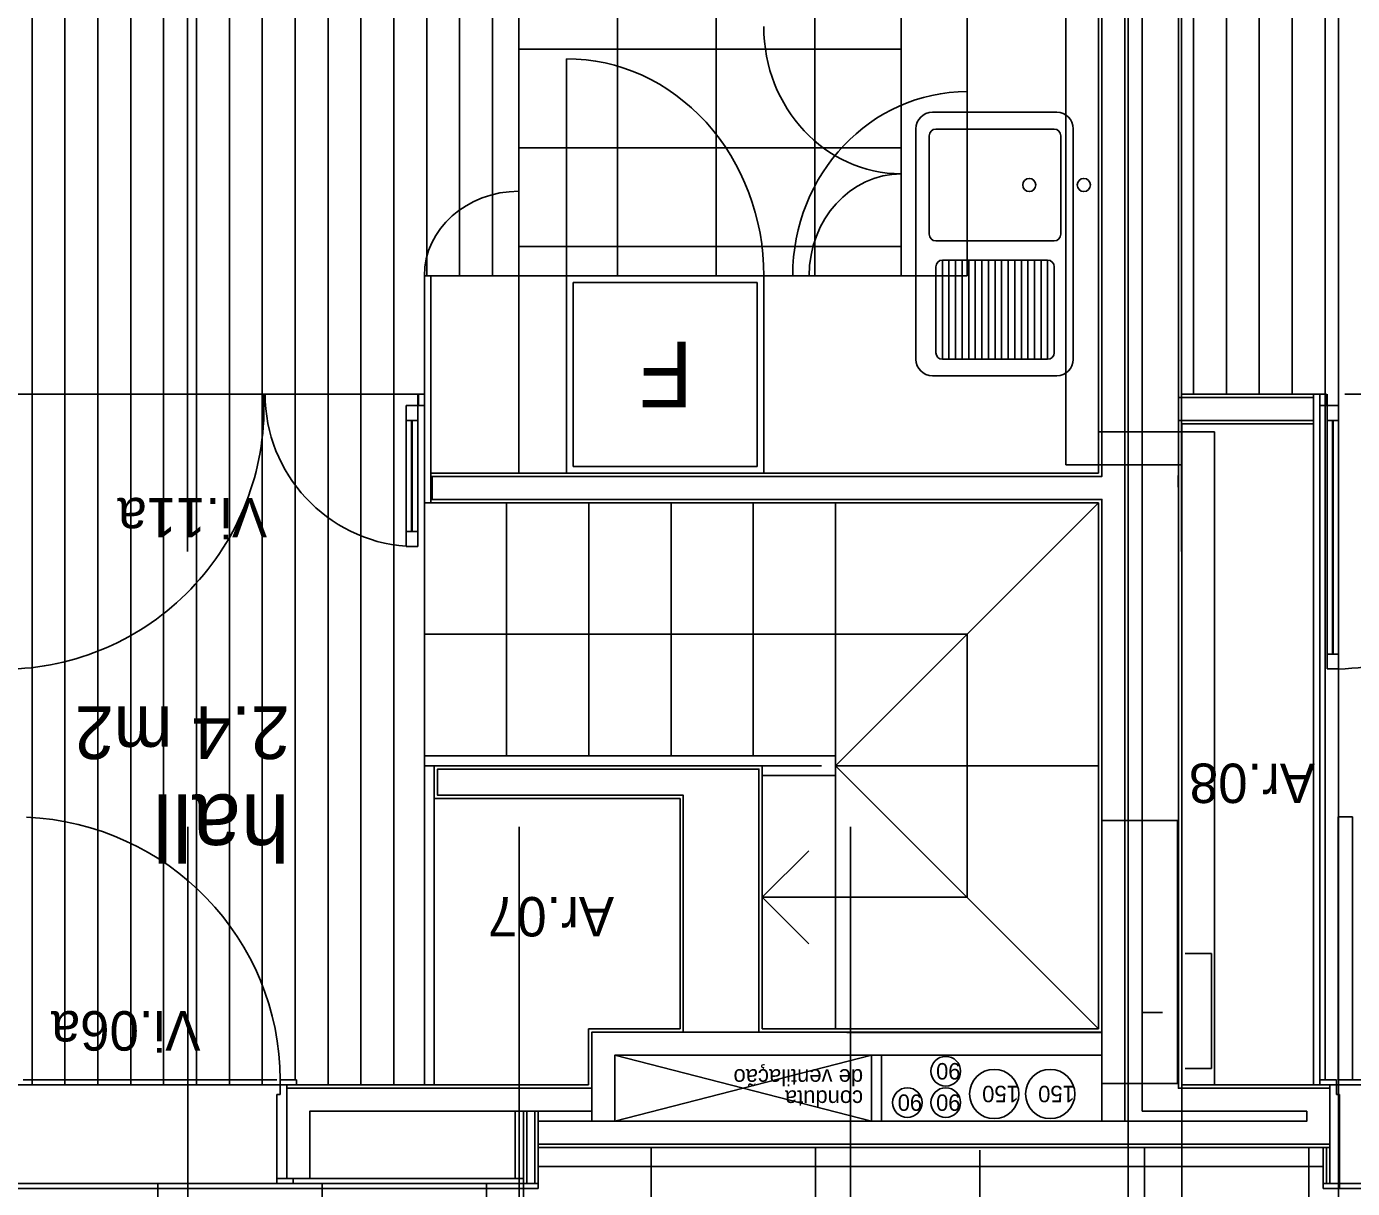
# Model space of a CAD drawing. Extents: x 1248 to 1356, y -443 to -224.
# Drawn here: x 1308.119 to 1312.151, y -237.241 to -233.707 of the extents above; entities that cross this region are included whole.
import ezdxf

# ---------------------------------------------------------------- set-up
doc = ezdxf.new("R2010")
doc.units = 0
for name, color, linetype in [('corte', 7, 'Continuous'), ('estereoctomias', 7, 'Continuous'), ('Level 1', 7, 'Continuous'), ('Level 10', 7, 'Continuous'), ('Level 11', 7, 'Continuous'), ('Level 13', 7, 'Continuous'), ('Level 2', 7, 'Continuous'), ('Level 21', 7, 'Continuous'), ('Level 3', 7, 'Continuous'), ('Level 36', 7, 'Continuous'), ('Level 4', 7, 'Continuous'), ('Level 40', 7, 'Continuous'), ('Level 41', 7, 'Continuous'), ('Level 59', 7, 'Continuous'), ('Level 60', 7, 'Continuous'), ('mob-fixo', 7, 'Continuous'), ('projeccao', 7, 'Continuous'), ('revestimentos', 7, 'Continuous'), ('vermelhos-cont', 7, 'Continuous'), ('vermelhos-tracej', 7, 'Continuous')]:
    doc.layers.add(name, color=color, linetype=linetype)

msp = doc.modelspace()

# ---------------------------------------------------------------- linework, layer by layer
at = {"layer": 'corte'}
for p, q in [((1311.6219, -235.1452), (1311.6219, -231.934)), ((1311.6219, -234.8352), (1311.6219, -231.934)), ((1311.389, -232.2659), (1311.389, -235.0752)), ((1311.459, -232.7639), (1311.459, -236.1213)), ((1311.5119, -236.1213), (1311.5119, -232.7639)), ((1311.6219, -236.9359), (1311.6219, -234.9052)), ((1311.389, -235.1452), (1311.389, -237.0363)), ((1311.6219, -236.9359), (1311.6219, -235.1452)), ((1311.459, -236.1213), (1311.459, -237.0363)), ((1311.5119, -236.1213), (1311.5119, -237.0059)), ((1309.8383, -236.9359), (1309.8383, -236.7652)), ((1309.9083, -237.0363), (1309.9083, -236.8352)), ((1309.9083, -236.8352), (1311.389, -236.8352)), ((1310.689, -236.8352), (1310.689, -237.0363)), ((1310.719, -236.8352), (1310.719, -237.0363)), ((1312.0819, -237.1063), (1312.0819, -236.9259)), ((1308.9104, -237.2109), (1308.9104, -236.9359)), ((1308.9804, -237.2109), (1308.9804, -237.0059)), ((1309.8383, -237.0363), (1309.8383, -237.0059)), ((1312.0119, -237.0363), (1312.0119, -237.0059)), ((1309.6754, -237.1063), (1309.6754, -237.0363)), ((1311.459, -237.0363), (1312.0119, -237.0363)), ((1311.4019, -237.1063), (1309.6754, -237.1063)), ((1308.9804, -237.2109), (1308.9104, -237.2109))]:
    msp.add_line(p, q, dxfattribs=at)
msp.add_lwpolyline([(1311.389, -236.9213), (1311.619, -236.9213), (1311.619, -236.1213), (1311.389, -236.1213)], close=True, dxfattribs=at)
at = {"layer": 'estereoctomias'}
for p, q in [((1308.8804, -237.2259), (1308.0804, -237.2259)), ((1312.9119, -237.2259), (1312.1119, -237.2259))]:
    msp.add_line(p, q, dxfattribs=at)
for points in [[(1311.459, -232.7639), (1311.459, -236.1213), (1311.389, -236.1213), (1311.389, -235.1452), (1309.3528, -235.1452), (1309.3528, -235.0752), (1311.389, -235.0752), (1311.389, -232.7639)], [(1311.5119, -232.7639), (1311.6219, -232.7639), (1311.6219, -235.0752), (1311.6214, -235.073), (1311.6219, -235.1452), (1311.6219, -235.1452), (1311.6219, -236.1213), (1311.5119, -236.1213)], [(1311.5119, -232.7639), (1311.6219, -232.7639), (1311.6219, -234.8352), (1312.0319, -234.8352), (1312.0319, -234.9052), (1311.6219, -234.9052), (1311.6219, -236.1213), (1311.5119, -236.1213)], [(1310.3464, -236.7652), (1310.3464, -235.9652), (1309.369, -235.9652), (1309.369, -236.0452), (1310.1164, -236.0452), (1310.1164, -236.7652)], [(1311.389, -236.7652), (1311.389, -236.8352), (1309.9083, -236.8352), (1309.9083, -237.0363), (1309.8383, -237.0363), (1309.8383, -236.7652)], [(1310.719, -236.8352), (1310.719, -237.0363), (1310.689, -237.0363), (1310.689, -236.8352)], [(1311.5119, -237.0059), (1311.5119, -236.9213), (1311.6219, -236.9213), (1311.6219, -236.9359), (1312.0819, -236.9359), (1312.0819, -237.1063), (1309.6754, -237.1063), (1309.6754, -237.0363), (1312.0119, -237.0363), (1312.0119, -237.0059)], [(1311.459, -237.0363), (1311.459, -236.9213), (1311.389, -236.9213), (1311.389, -237.0363)], [(1309.8383, -236.9359), (1309.8383, -237.0059), (1308.9804, -237.0059), (1308.9804, -237.2109), (1308.9104, -237.2109), (1308.9104, -236.9359)]]:
    msp.add_lwpolyline(points, close=True, dxfattribs=at)
at = {"layer": 'Level 1'}
for p, q in [((1312.0319, -234.9152), (1312.0319, -234.8252)), ((1311.6219, -234.8352), (1312.0319, -234.8352)), ((1312.0319, -234.9052), (1311.6219, -234.9052)), ((1309.349, -235.0652), (1309.349, -235.1552)), ((1311.389, -235.0752), (1309.349, -235.0752)), ((1311.389, -235.1452), (1309.349, -235.1452)), ((1310.3464, -235.9652), (1309.369, -235.9652)), ((1309.369, -235.9652), (1309.369, -236.0452)), ((1310.3464, -236.7652), (1310.3464, -235.9652)), ((1309.369, -236.0452), (1310.1164, -236.0452)), ((1310.1164, -236.7652), (1310.1164, -236.0452)), ((1311.51, -236.7052), (1311.57, -236.7052)), ((1311.5129, -236.7052), (1311.5729, -236.7052)), ((1309.8383, -236.7652), (1311.389, -236.7672)), ((1309.8383, -236.9359), (1308.9104, -236.9359)), ((1311.6219, -236.9359), (1312.0819, -236.9359)), ((1309.8383, -237.0059), (1308.9804, -237.0059)), ((1311.5119, -237.0059), (1312.0119, -237.0059)), ((1309.8383, -237.0363), (1309.6754, -237.0363)), ((1311.389, -237.0363), (1309.9083, -237.0363)), ((1312.0819, -237.1063), (1309.8512, -237.1063))]:
    msp.add_line(p, q, dxfattribs=at)
at = {"layer": 'Level 10'}
for p, q in [((1308.1362, -232.2759), (1308.1362, -236.9259)), ((1308.2362, -232.2759), (1308.2362, -236.9259)), ((1308.3362, -232.2759), (1308.3362, -236.9259)), ((1308.4362, -232.2759), (1308.4362, -236.9259)), ((1308.5362, -232.2759), (1308.5362, -236.9259)), ((1308.6362, -232.2759), (1308.6362, -236.9259)), ((1308.7362, -232.2759), (1308.7362, -236.9259)), ((1308.8362, -232.2759), (1308.8362, -236.9259)), ((1308.9362, -232.2759), (1308.9362, -236.9109)), ((1309.0362, -232.2759), (1309.0362, -236.9259)), ((1309.1362, -232.2759), (1309.1362, -236.9259)), ((1309.2362, -232.2759), (1309.2362, -236.9259)), ((1309.3362, -232.2759), (1309.3362, -234.4652)), ((1309.4362, -232.2759), (1309.4362, -234.4652)), ((1309.5362, -232.2759), (1309.5362, -234.4652)), ((1309.6162, -232.2759), (1309.6162, -234.4652)), ((1309.9162, -232.2759), (1309.9162, -234.4652)), ((1310.2162, -232.2759), (1310.2162, -234.4652)), ((1310.5162, -232.2759), (1310.5162, -234.4652)), ((1311.6677, -232.2759), (1311.6677, -234.8252)), ((1311.7677, -232.2759), (1311.7677, -234.8252)), ((1311.8677, -232.2759), (1311.8677, -234.8252)), ((1311.9677, -232.2759), (1311.9677, -234.8252)), ((1312.0677, -232.2759), (1312.0677, -236.9109)), ((1308.8904, -236.9259), (1308.0704, -236.9259)), ((1312.9219, -236.9259), (1312.1019, -236.9259)), ((1310.0183, -237.1163), (1310.0183, -238.724)), ((1310.5183, -237.1163), (1310.5183, -238.724)), ((1311.0183, -237.124), (1311.0183, -238.724)), ((1311.5183, -237.1163), (1311.5183, -238.724)), ((1312.0183, -237.1163), (1312.0183, -238.724)), ((1309.6754, -237.174), (1312.0619, -237.174)), ((1308.5183, -237.2259), (1308.5183, -238.624)), ((1309.0183, -237.2259), (1309.0183, -238.624)), ((1309.5183, -237.2259), (1309.5183, -238.624))]:
    msp.add_line(p, q, dxfattribs=at)
at = {"layer": 'Level 11'}
for p, q in [((1310.3412, -234.4852), (1309.7812, -234.4852)), ((1309.7812, -234.4852), (1309.7812, -235.0452)), ((1310.3412, -234.4852), (1310.3412, -235.0452)), ((1309.7812, -235.0452), (1310.3412, -235.0452))]:
    msp.add_line(p, q, dxfattribs=at)
at = {"layer": 'Level 13'}
for p, q in [((1309.349, -234.4652), (1309.329, -234.4652)), ((1309.329, -234.4652), (1309.329, -235.1552)), ((1309.349, -234.4652), (1309.349, -235.0652)), ((1309.3109, -234.8602), (1309.3109, -234.8252)), ((1309.3109, -234.8252), (1309.3309, -234.8252)), ((1312.0519, -234.8252), (1312.0319, -234.8252)), ((1312.0719, -234.8252), (1312.0519, -234.8252)), ((1312.0519, -234.8252), (1312.0519, -236.9259)), ((1312.0719, -234.8252), (1312.0719, -234.8602)), ((1309.2739, -234.8602), (1309.3089, -234.8602)), ((1309.2739, -234.8602), (1309.2739, -235.288)), ((1309.3089, -234.8602), (1309.3089, -235.288)), ((1309.3109, -234.8602), (1309.3309, -234.8602)), ((1312.0719, -234.8602), (1312.0519, -234.8602)), ((1312.0739, -234.8602), (1312.0739, -235.661)), ((1312.1089, -234.8602), (1312.0739, -234.8602)), ((1312.1089, -234.8602), (1312.1089, -235.661)), ((1309.2739, -234.9052), (1309.3089, -234.9052)), ((1312.0319, -234.9152), (1312.0319, -236.9259)), ((1312.1089, -234.9052), (1312.0739, -234.9052)), ((1312.0519, -235.0652), (1312.0519, -236.9259)), ((1309.349, -235.1552), (1309.329, -235.1552)), ((1309.3089, -235.243), (1309.2739, -235.243)), ((1309.3089, -235.288), (1309.2739, -235.288)), ((1312.1089, -235.616), (1312.0739, -235.616)), ((1312.1089, -235.661), (1312.0739, -235.661)), ((1309.329, -235.9552), (1309.329, -236.9259)), ((1309.359, -235.9552), (1309.329, -235.9552)), ((1309.359, -235.9552), (1309.359, -236.9259)), ((1312.1069, -236.1109), (1312.1069, -236.9109)), ((1312.1509, -236.1109), (1312.1069, -236.1109)), ((1312.1509, -236.9109), (1312.1509, -236.1109)), ((1308.8904, -236.9109), (1308.9404, -236.9109)), ((1308.8904, -236.9549), (1308.8904, -236.9259)), ((1308.9104, -236.9259), (1308.9104, -237.2109)), ((1312.0819, -236.9259), (1312.0819, -237.2259)), ((1312.1019, -236.9549), (1312.1019, -236.9259)), ((1312.1069, -236.9109), (1312.1509, -236.9109)), ((1308.8804, -237.2109), (1308.8804, -236.9549)), ((1308.8804, -236.9549), (1308.8904, -236.9549)), ((1312.1119, -236.9549), (1312.1019, -236.9549)), ((1312.1119, -236.9549), (1312.1119, -237.2259)), ((1309.6304, -237.0059), (1309.6304, -237.2259)), ((1309.6404, -237.2259), (1309.6404, -237.0059)), ((1309.6654, -237.2259), (1309.6654, -237.0059)), ((1309.6754, -237.2059), (1309.6754, -237.0059)), ((1312.0619, -237.2409), (1312.0619, -237.1163)), ((1312.0719, -237.1163), (1312.0719, -237.2259)), ((1309.6304, -237.2109), (1308.8804, -237.2109)), ((1308.8804, -237.2109), (1308.8804, -237.2259)), ((1308.9304, -237.2109), (1308.9304, -237.2259)), ((1309.6304, -237.2109), (1309.6304, -237.2259)), ((1309.6754, -237.2059), (1309.6754, -237.2259)), ((1308.9304, -237.2259), (1308.8804, -237.2259)), ((1309.6304, -237.2259), (1308.9204, -237.2259)), ((1309.6304, -237.2259), (1308.9204, -237.2259)), ((1309.6304, -237.2259), (1308.9304, -237.2259)), ((1309.6304, -237.2259), (1309.6304, -237.2409)), ((1309.6304, -237.2259), (1309.6754, -237.2259)), ((1309.6304, -237.2409), (1309.6754, -237.2409)), ((1309.6754, -237.2259), (1309.6754, -237.2409)), ((1312.0619, -237.2259), (1312.1119, -237.2259)), ((1312.1119, -237.2409), (1312.0619, -237.2409)), ((1312.1119, -237.2259), (1312.1119, -237.2409))]:
    msp.add_line(p, q, dxfattribs=at)
for points in [[(1308.9404, -236.9109), (1308.8904, -236.9109), (1308.8904, -236.9259), (1308.9404, -236.9259)], [(1312.1019, -236.9259), (1312.0519, -236.9259), (1312.0519, -236.9109), (1312.1019, -236.9109)]]:
    msp.add_lwpolyline(points, close=True, dxfattribs=at)
at = {"layer": 'Level 2'}
for p, q in [((1310.779, -232.2759), (1310.779, -234.4652)), ((1311.2441, -234.0191), (1310.8841, -234.0191)), ((1310.8641, -234.0391), (1310.8641, -234.3391)), ((1311.2641, -234.3391), (1311.2641, -234.0391)), ((1310.8841, -234.3591), (1311.2441, -234.3591)), ((1311.2241, -234.4175), (1310.9041, -234.4175)), ((1310.9041, -234.4175), (1310.9041, -234.7191)), ((1310.9241, -234.4175), (1310.9241, -234.7191)), ((1310.9441, -234.4175), (1310.9441, -234.7191)), ((1310.9641, -234.4175), (1310.9641, -234.7191)), ((1310.9841, -234.4175), (1310.9841, -234.7191)), ((1311.0041, -234.4175), (1311.0041, -234.7191)), ((1311.0241, -234.4175), (1311.0241, -234.7191)), ((1311.0441, -234.4175), (1311.0441, -234.7191)), ((1311.0641, -234.4175), (1311.0641, -234.7191)), ((1311.0841, -234.4175), (1311.0841, -234.7191)), ((1311.1041, -234.4175), (1311.1041, -234.7191)), ((1311.1241, -234.4175), (1311.1241, -234.7191)), ((1311.1441, -234.4175), (1311.1441, -234.7191)), ((1311.1641, -234.4175), (1311.1641, -234.7191)), ((1311.1841, -234.4175), (1311.1841, -234.7191)), ((1311.2041, -234.4175), (1311.2041, -234.7191)), ((1311.2241, -234.4175), (1311.2241, -234.7191)), ((1310.779, -234.4652), (1309.349, -234.4652)), ((1310.7662, -234.4652), (1309.4862, -234.4652)), ((1310.7662, -234.4652), (1309.4862, -234.4652)), ((1309.7612, -234.4652), (1309.7612, -235.0652)), ((1309.7612, -234.4652), (1309.7612, -235.0652)), ((1310.3612, -234.4652), (1310.3612, -235.0652)), ((1310.3612, -234.4652), (1310.3612, -235.0652)), ((1310.8841, -234.4375), (1310.8841, -234.6991)), ((1311.2441, -234.4375), (1311.2441, -234.6991)), ((1311.2241, -234.7191), (1310.9041, -234.7191)), ((1309.329, -235.9552), (1309.329, -235.1552)), ((1309.579, -235.9252), (1309.579, -235.1552)), ((1309.829, -235.9252), (1309.829, -235.1552)), ((1310.079, -235.9252), (1310.079, -235.1552)), ((1310.329, -235.9252), (1310.329, -235.1552)), ((1310.579, -235.9252), (1310.579, -235.1552)), ((1310.579, -235.9552), (1311.379, -235.1552)), ((1309.329, -235.5552), (1310.979, -235.5552)), ((1310.979, -236.3552), (1310.979, -235.5552)), ((1310.579, -235.9252), (1309.329, -235.9252)), ((1310.5364, -235.9552), (1309.329, -235.9552)), ((1310.5364, -235.9552), (1309.3317, -235.9552)), ((1310.579, -235.9252), (1310.579, -235.9852)), ((1311.379, -235.9552), (1310.579, -235.9552)), ((1310.579, -235.9552), (1311.379, -236.7552)), ((1310.579, -235.9852), (1310.3564, -235.9852)), ((1310.579, -236.7552), (1310.579, -235.9852)), ((1310.4978, -236.2137), (1310.3564, -236.3552)), ((1310.979, -236.3552), (1310.3564, -236.3552)), ((1310.4978, -236.4966), (1310.3564, -236.3552))]:
    msp.add_line(p, q, dxfattribs=at)
for points in [[(1310.8736, -233.9679), (1311.252, -233.9679)], [(1310.8236, -234.7193), (1310.8236, -234.0179)], [(1311.302, -234.0179), (1311.302, -234.7193)], [(1311.252, -234.7693), (1310.8736, -234.7693)]]:
    msp.add_lwpolyline(points, dxfattribs=at)
for centre in [(1311.1681, -234.1891), (1311.3341, -234.1891)]:
    msp.add_circle(centre, 0.0199, dxfattribs=at)
for centre, radius, start, end in [((1310.8736, -234.0179), 0.05, 90, 180), ((1311.252, -234.0179), 0.05, 360, 90), ((1310.8841, -234.0391), 0.02, 90, 180), ((1311.2441, -234.0391), 0.02, 360, 90), ((1310.8841, -234.3391), 0.02, 180, 270), ((1311.2441, -234.3391), 0.02, 270, 0), ((1310.9041, -234.4375), 0.02, 90, 180), ((1311.2241, -234.4375), 0.02, 0, 90), ((1310.9041, -234.6991), 0.02, 180, 270), ((1311.2241, -234.6991), 0.02, 270, 0), ((1310.8736, -234.7193), 0.05, 180, 270), ((1311.252, -234.7193), 0.05, 270, 360)]:
    msp.add_arc(centre, radius, start, end, dxfattribs=at)
at = {"layer": 'Level 21'}
for p, q in [((1309.6162, -233.7759), (1310.779, -233.7759)), ((1309.6162, -234.0759), (1310.779, -234.0759)), ((1309.6162, -234.3759), (1310.779, -234.3759))]:
    msp.add_line(p, q, dxfattribs=at)
at = {"layer": 'Level 3'}
for p in [(1310.979, -232.2759), (1310.779, -234.4652)]:
    msp.add_line(p, (1310.979, -234.4652), dxfattribs=at)
at = {"layer": 'Level 36'}
for p, q in [((1309.2904, -234.9052), (1309.2904, -235.243)), ((1309.2924, -234.9052), (1309.2924, -235.243)), ((1312.0904, -234.9052), (1312.0904, -235.616)), ((1312.0924, -234.9052), (1312.0924, -235.616))]:
    msp.add_line(p, q, dxfattribs=at)
at = {"layer": 'Level 4'}
for p, q in [((1309.7612, -233.8052), (1309.7612, -234.4652)), ((1309.6162, -234.4652), (1309.6162, -234.2052)), ((1309.6162, -234.4652), (1309.6162, -235.0652)), ((1308.0404, -234.8252), (1309.3294, -234.8252)), ((1309.3089, -234.8602), (1309.3089, -234.8252)), ((1312.0739, -234.8602), (1312.0739, -234.8252)), ((1312.1273, -234.8252), (1313.4163, -234.8252)), ((1311.6419, -236.5259), (1311.7219, -236.5259)), ((1311.7219, -236.5259), (1311.7219, -236.8759)), ((1311.6419, -236.8759), (1311.7219, -236.8759)), ((1308.8804, -236.9109), (1308.1094, -236.9109)), ((1312.9119, -236.9109), (1312.1409, -236.9109)), ((1309.6054, -237.0059), (1309.6054, -237.2109)), ((1308.0804, -237.2409), (1309.6304, -237.2409)), ((1309.6304, -237.2259), (1309.6304, -237.9259)), ((1312.1119, -237.2409), (1313.6619, -237.2409))]:
    msp.add_line(p, q, dxfattribs=at)
for centre, major_axis, ratio, start_param, end_param in [((1310.779, -233.7072), (0, -0.448), 0.933036, 4.712389, 6.283185), ((1309.7612, -234.4652), (0, -0.66), 0.909091, 1.570796, 3.141593), ((1310.979, -234.4652), (0, -0.56), 0.946429, 3.141593, 4.712389), ((1310.779, -234.4652), (0, -0.31), 0.903226, 3.141593, 4.712389), ((1308.0844, -236.9109), (-0.806, 0), 0.992512, 3.141593, 4.668897)]:
    msp.add_ellipse(centre, major_axis=major_axis, ratio=ratio, start_param=start_param, end_param=end_param, dxfattribs=at)
at = {"layer": 'Level 41'}
for p, q in [((1310.689, -237.0363), (1309.9083, -236.8352)), ((1309.9083, -237.0363), (1310.689, -236.8352))]:
    msp.add_line(p, q, dxfattribs=at)
for centre, radius in [((1310.9143, -236.8843), 0.045), ((1311.0616, -236.9535), 0.075), ((1311.2318, -236.9535), 0.075), ((1310.7975, -236.9797), 0.045), ((1310.9143, -236.9797), 0.045)]:
    msp.add_circle(centre, radius, dxfattribs=at)
at = {"layer": 'Level 59'}
msp.add_lwpolyline([(1312.108, -245.3846), (1306.9649, -245.3846), (1306.9649, -230.4331), (1312.108, -230.4331)], close=True, dxfattribs=at)
at = {"layer": 'mob-fixo'}
for p, q in [((1311.279, -232.609), (1311.279, -235.0402)), ((1311.379, -234.9402), (1311.7319, -234.9402)), ((1311.7319, -236.9259), (1311.7319, -234.9402)), ((1311.279, -235.0402), (1311.6319, -235.0402))]:
    msp.add_line(p, q, dxfattribs=at)
at = {"layer": 'projeccao'}
for centre, radius, start, end in [((1308.0452, -234.8658), 0.7962, 272.1092, 2.9297), ((1309.3089, -234.8252), 0.4641, 180, 265.6752), ((1312.0796, -234.8658), 0.7962, 272.1092, 2.9297)]:
    msp.add_arc(centre, radius, start, end, dxfattribs=at)
msp.add_ellipse((1309.6162, -234.4652), major_axis=(-0.2871, 0), ratio=0.895522, start_param=4.712389, end_param=6.283185, dxfattribs=at)
at = {"layer": 'revestimentos'}
for p, q in [((1311.6312, -234.8252), (1311.6312, -231.924)), ((1311.6312, -234.8252), (1311.6312, -231.924)), ((1311.379, -232.2759), (1311.379, -235.0652)), ((1311.6312, -234.8252), (1312.0319, -234.8252)), ((1312.0319, -234.9152), (1311.6319, -234.9152)), ((1311.6319, -236.9259), (1311.6319, -234.9152)), ((1311.379, -235.1552), (1309.349, -235.1552)), ((1311.379, -235.1552), (1311.379, -236.7552)), ((1311.6319, -236.9259), (1311.6319, -235.1552)), ((1310.3564, -235.9552), (1309.359, -235.9552)), ((1309.359, -235.9552), (1309.359, -236.0552)), ((1310.3564, -236.7552), (1310.3564, -235.9552)), ((1309.359, -236.0552), (1310.1064, -236.0552)), ((1310.1064, -236.0552), (1310.1064, -236.7552)), ((1309.8283, -236.7552), (1310.1064, -236.7552)), ((1309.8283, -236.9259), (1309.8283, -236.7552)), ((1310.3564, -236.7552), (1311.379, -236.7552)), ((1309.8283, -236.9259), (1308.9104, -236.9259)), ((1311.6319, -236.9259), (1312.0819, -236.9259)), ((1312.0819, -237.1163), (1309.6754, -237.1163))]:
    msp.add_line(p, q, dxfattribs=at)
msp.add_lwpolyline([(1309.349, -235.0652), (1311.379, -235.0652)], dxfattribs=at)
at = {"layer": 'vermelhos-cont'}
msp.add_line((1311.469, -250.7923), (1311.469, -229.6198), dxfattribs=at)
at = {"layer": 'vermelhos-tracej'}
for p, q in [((1308.6087, -235.3039), (1308.6087, -224.3117)), ((1311.6312, -235.3039), (1311.6312, -224.3117)), ((1308.6098, -246.757), (1308.6098, -236.1407)), ((1309.6173, -246.757), (1309.6173, -236.1407)), ((1310.6248, -246.757), (1310.6248, -236.1407)), ((1311.6323, -246.757), (1311.6323, -236.1407))]:
    msp.add_line(p, q, dxfattribs=at)

# ---------------------------------------------------------------- texts
at = {"layer": 'Level 11'}
msp.add_text('F', height=0.2, rotation=180, dxfattribs=at).set_placement((1310.1451, -234.6651))
at = {"layer": 'Level 40'}
for s, p in [('Vi.11a', (1308.851, -235.1408)), ('Ar.08', (1312.037, -235.9486)), ('Ar.07', (1309.9058, -236.3544)), ('Vi.06a', (1308.6484, -236.7015))]:
    msp.add_text(s, height=0.12, rotation=180, dxfattribs=at).set_placement(p)
at = {"layer": 'Level 41'}
for s, p in [('de ventilação ', (1310.663, -236.878)), ('90', (1310.9593, -236.8593)), ('150', (1311.1366, -236.9285)), ('150', (1311.3068, -236.9285)), ('conduta', (1310.663, -236.9424)), ('90', (1310.8425, -236.9547)), ('90', (1310.9593, -236.9547))]:
    msp.add_text(s, height=0.05, rotation=180, dxfattribs=at).set_placement(p)
at = {"layer": 'Level 60'}
for s, height, p in [('2.4 m2', 0.16, (1308.9198, -235.7748)), ('hall', 0.2, (1308.9198, -236.0426))]:
    msp.add_text(s, height=height, rotation=180, dxfattribs=at).set_placement(p)

doc.saveas('drawing.dxf')
